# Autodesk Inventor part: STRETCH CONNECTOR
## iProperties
Created: 2006-12
Part Number: STRETCH CONNECTOR
Document SubType Name: Modeling
Designer: Andy Moles
Density: 1 g/cm^3
Author: Andy Moles
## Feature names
1. Base1
2. Hole1
